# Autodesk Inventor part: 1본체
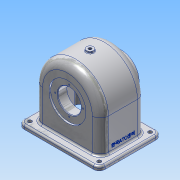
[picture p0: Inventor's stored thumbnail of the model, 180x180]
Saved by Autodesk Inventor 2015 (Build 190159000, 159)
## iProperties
Created: 2022-09
Part Number: 1본체
Material: 알루미늄 6061
Document SubType Name: Modeling
Designer: 학생용
Density: 2.7 g/cm^3
Appearance: 알루미늄 - 평지
Mass: 785.035 g
Surface Area: 1042.06 cm^2
Volume: 290.754 cm^3
Author: 학생용
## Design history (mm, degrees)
sketch "스케치1"
  geometry: L1 (-57, -39)-(57, -39); L2 (57, -39)-(57, 39); L3 (57, 39)-(-57, 39); L4 (-57, 39)-(-57, -39); L5 (-57, -39)-(57, 39); L6 (57, -39)-(-57, 39); 1 further point
  constraints: 12 end point, 2 midpoint, 2 parallel, 1 horizontal, 1 perpendicular
  dimensions: "d0" = 78 distance between parallel lines of L1 L3; "d1" = 114 distance between parallel lines of L4 L2
extrude "돌출1" new body sketch "스케치1" distance "d2" = 121; taper "d3" = 0 deg
fillet "모깎기1" dims "d4" = 57
feature "쉘1" dims "d5" = 5
sketch "스케치2"
  geometry: L1 (70, -54)-(-70, -54); L2 (-70, -54)-(-70, 54); L3 (-70, 54)-(70, 54); L4 (70, 54)-(70, -54); L5 (70, -54)-(-70, 54); L6 (-70, -54)-(70, 54); L7 (-57, -39)-(-57, 39) reference; L8 (-52, -34)-(-52, 34) reference; L9 (52, -34)-(-52, -34); L10 (-52, -34)-(-52, 34); L11 (-52, 34)-(52, 34); L12 (52, 34)-(52, -34); L13 (52, -34)-(-52, 34); L14 (-52, -34)-(52, 34); C1 r 3.3 at (60, 44); C2 r 3.3 at (-60, 44); C3 r 3.3 at (60, -44); C4 r 3.3 at (-60, -44); 1 further point
  constraints: 24 end point, 4 centre point, 4 midpoint, 4 parallel, 3 horizontal, 2 perpendicular, 1 vertical, 6 other
  dimensions: "d6" = 108 distance between parallel lines of L1 L3; "d7" = 140 distance between parallel lines of L4 L2; "d8" = 6.6 diameter of C1; "d9" = 10 distance from line of L3 C1.centre; "d10" = 10 distance from line of L4 C1.centre; "d13" = 120 distance of C1.centre C2.centre; "d16" = 88 distance of C1.centre C3.centre
extrude "돌출2" join sketch "스케치2" distance "d19" = 7; taper "d20" = 0 deg
sketch "스케치3"
  geometry: L1 (70, 64)-(-70, 64) reference; C1 r 31 at (0, 0); 1 further point
  constraints: 1 centre point, 1 vertical alignment
  dimensions: "d21" = 62 diameter of C1; "d22" = 64 distance from line of L1 C1.centre
extrude "돌출3" join sketch "스케치3" distance "d23" = 15; taper "d24" = 0 deg
sketch "스케치4"
  geometry: C1 r 31 at (0, 0) reference; C2 r 20 at (0, 0); 1 further point
  constraints: 1 centre point, 1 coincident
  dimensions: "d25" = 40 diameter of C2
extrude "돌출4" cut sketch "스케치4" distance "d26" = 16; taper "d27" = 0 deg
sketch "스케치5"
  geometry: C1 r 20 at (0, 0) reference; C2 r 17.5 at (0, 0); 1 further point
  constraints: 1 centre point, 1 coincident
  dimensions: "d28" = 35 diameter of C2
extrude "돌출5" cut sketch "스케치5" stored distance "d29" = 16; taper "d30" = 0 deg
node "작업 평면1"
sketch "스케치6"
  geometry: L1 (-52, 64)-(52, 64) reference; C1 r 28 at (0, 0); 2 further points
  constraints: 1 centre point, 1 midpoint, 1 vertical alignment
  dimensions: "d32" = 56 diameter of C1; "d33" = 64 distance from line of L1 C1.centre
extrude "돌출6" join sketch "스케치6" distance "d34" = 14; taper "d35" = 30 deg
sketch "스케치7"
  geometry: L1 (-52, 64)-(-52, 0) reference; L2 (52, 0)-(52, 64) reference; L3 (52, 64)-(70, 64) reference; L4 (70, 64)-(70, 57) reference; L5 (70, 57)-(57, 57) reference; L6 (57, 57)-(57, 0) reference; L7 (-57, 0)-(-57, 57) reference; L8 (-57, 57)-(-70, 57) reference; L9 (-70, 57)-(-70, 64) reference; L10 (-70, 64)-(-52, 64) reference; C1 r 28 at (0, 0) reference; C2 r 20 at (0, 0); A1 r 52 centre (0, 0) between (-52, 0) and (52, 0) reference; A2 r 57 centre (0, 0) between (-57, 0) and (57, 0) reference; 1 further point
  constraints: 1 centre point, 1 coincident
  dimensions: "d36" = 40 diameter of C2
extrude "돌출7" cut sketch "스케치7" distance "d37" = 16; taper "d38" = 0 deg
sketch "스케치8"
  geometry: C1 r 20 at (0, 0) reference; C2 r 32 at (0, 0); 1 further point
  constraints: 1 centre point, 1 coincident
  dimensions: "d39" = 64 diameter of C2
extrude "돌출8" cut sketch "스케치8" stored distance "d40" = 16; taper "d41" = 0 deg
node "작업 평면2"
sketch "스케치9"
  geometry: C1 r 6 at (0, 0); 1 further point
  constraints: 1 centre point, 1 coincident
  dimensions: "d43" = 12 diameter of C1
extrude "돌출9" join sketch "스케치9" stored distance "d44" = 0; taper "d45" = 0 deg
fillet "모깎기2" dims "d46" = 14, "d47" = 9, "d48" = 0.6, "d49" = 1, "d50" = 3
fillet "모깎기3" dims "d51" = 10, "d86" = 3
chamfer "모따기1" distance "d52" = 1; stored, may be unused: second distance "d53" = 2, angle "d54" = 45 deg
sketch "스케치10" dims "d55" = 48
  geometry: C1 r 32 at (0, 0) reference; 6 further points
  constraints: 2 vertical alignment, 1 coincident, 7 other
  dimensions: "d58" = 360 deg dimension on C1.centre point (0, 24) (derived)
hole "구멍1" sketch "스케치10" at (0, 24), (-24, 0), (0, -24), (24, 0) diameter "d60" = 2.459; stored, may be unused: countersink angle "d64" = 90 deg, drill point angle "d66" = 118 deg; dims "d61" = 7, "d62" = 4, "d63" = 2, "d65" = 9
sketch "스케치11" dims "d67" = 48
  geometry: C1 r 31 at (0, 0) reference; 6 further points
  constraints: 2 vertical alignment, 1 coincident, 7 other
  dimensions: "d70" = 360 deg dimension on C1.centre point (0, -24) (derived)
hole "구멍2" sketch "스케치11" at (0, -24), (24, 0), (0, 24), (-24, 0) diameter "d72" = 2.459; stored, may be unused: countersink angle "d76" = 90 deg, drill point angle "d78" = 118 deg; dims "d73" = 7, "d74" = 4, "d75" = 2, "d77" = 9
sketch "스케치12"
  geometry: 2 further points
  constraints: 1 coincident
hole "구멍3" sketch "스케치12" at (0, 0) diameter "d79" = 5.188; stored, may be unused: countersink angle "d83" = 90 deg, drill point angle "d85" = 118 deg; dims "d80" = 15, "d81" = 4, "d82" = 2, "d84" = 15
sketch "스케치13"
  geometry: L1 (64, -19)-(64, 69) reference; L2 (0, -14)-(54, -14) reference; 2 further points
  constraints: 1 other
  dimensions: "d87" = 17 distance from line of L1 point (47, 25); "d88" = 39 distance from line of point (47, 25) L2
extrude "돌출10" join sketch "스케치13" distance "d89" = 0.5; taper "d90" = 0 deg
node "솔리드1"
node "투영된 루프1"
node "절단 모서리 투영1"
other parameters: "d31" = 14, "d42" = 124
